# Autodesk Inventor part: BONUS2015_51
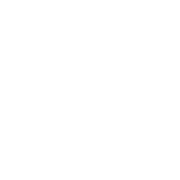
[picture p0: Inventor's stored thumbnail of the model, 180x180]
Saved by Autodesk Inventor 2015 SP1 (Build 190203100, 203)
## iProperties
Created: 2015-05
Part Number: BONUS2015_51
Material: Generisch
Document SubType Name: Modeling
Density: 1 g/cm^3
Appearance: Vorgabe
xx: 51
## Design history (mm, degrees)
